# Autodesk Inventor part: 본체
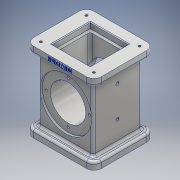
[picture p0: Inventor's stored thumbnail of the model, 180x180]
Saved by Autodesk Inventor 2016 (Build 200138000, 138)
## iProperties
Created: 2017-08
Part Number: 본체
Material: 알루미늄 6061
Document SubType Name: Modeling
Designer: USER
Mass: 790.515 g
Surface Area: 623.184 cm^2
Volume: 292.783 cm^3
Density: 2.7 g/cm^3
Appearance: 알루미늄 - 평지
Author: USER
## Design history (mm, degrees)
sketch "스케치1"
  geometry: L1 (0, 0)-(0, 10); L2 (0, 10)-(8, 10); L3 (8, 10)-(8, 98); L4 (8, 98)-(0, 98); L5 (0, 98)-(0, 108); L6 (0, 108)-(82, 108); L7 (82, 108)-(82, 98); L8 (82, 98)-(74, 98); L9 (74, 98)-(74, 10); L10 (74, 10)-(82, 10); L11 (82, 10)-(82, 0); L12 (82, 0)-(0, 0); L13 (8, 10)-(74, 10); L14 (8, 98)-(74, 98)
  constraints: 28 end point, 8 perpendicular, 4 point on line, 2 horizontal, 1 vertical
  dimensions: "d0" = 108 distance between parallel lines of L12 L6; "d1" = 10 distance between parallel lines of L4 L6; "d2" = 10 distance between parallel lines of L12 L2; "d7" = 8 distance of L3.end L4.end; "d11" = 82 distance between parallel lines of L7 L5; "d12" = 82 distance between parallel lines of L11 L1; "d13" = 66 distance between parallel lines of L3 L9; "d14" = 10 distance between parallel lines of L6 L8
extrude "돌출5" new body sketch "스케치1" stored distance "d73" = 74; taper "d74" = 0 deg
extrude "돌출6" join sketch "스케치1" stored distance "d75" = 92; taper "d76" = 0 deg
sketch "스케치12"
  geometry: 1 further point
node "작업 평면4"
sketch "스케치13"
  geometry: L1 (8, 10)-(8, 98) reference; L2 (8, 54)-(74, 54); L3 (74, 98)-(74, 10) reference; L4 (8, 54)-(8, 89); L5 (8, 89)-(11, 89); L6 (11, 89)-(11, 78); L7 (11, 78)-(71, 78); L8 (71, 78)-(71, 89); L9 (71, 89)-(74, 89); L10 (74, 89)-(74, 54); 1 further point
  constraints: 16 end point, 4 point on line, 3 perpendicular, 2 midpoint, 1 collinear, 1 horizontal
  dimensions: "d78" = 3 distance of L4.end L5.end; "d79" = 3 distance of L8.end L9.end; "d80" = 48 diameter of L7 L2; "d81" = 70 diameter of L5.end L2
revolve "회전2" sketch "스케치13" stored, may be unused: angle "d82" = 90 deg
sketch "스케치14"
  geometry: L1 (24, 19)-(68, 19); L2 (68, 19)-(68, 63); L3 (68, 63)-(24, 63); L4 (24, 63)-(24, 19); L5 (20, 15)-(72, 15); L6 (72, 15)-(72, 67); L7 (72, 67)-(20, 67); L8 (20, 67)-(20, 15); L9 (0, 0)-(0, 82) reference; L10 (0, 0)-(92, 0) reference; 8 further points
  constraints: 16 end point, 7 midpoint, 4 parallel, 2 horizontal, 2 horizontal alignment, 2 perpendicular, 2 vertical alignment
  dimensions: "d83" = 52 distance of L7.end L5.start; "d84" = 52 distance of L6.end L7.end; "d85" = 44 distance of L3.end L1.start; "d86" = 44 distance of L1.start L1.end
extrude "돌출7" cut sketch "스케치14" distance "d87" = 8; taper "d88" = 0 deg
extrude "돌출8" cut sketch "스케치14" stored distance "d89" = 8; taper "d90" = 0 deg; dims "d91" = 48, "d92" = 48
sketch "스케치15"
  geometry: L1 (22, -65)-(70, -65); L2 (70, -65)-(70, -17); L3 (70, -17)-(22, -17); L4 (22, -17)-(22, -65); L5 (0, -82)-(0, 0) reference; L6 (0, -82)-(92, -82) reference; 5 further points
  constraints: 8 end point, 4 midpoint, 2 parallel, 1 horizontal, 1 horizontal alignment, 1 perpendicular, 1 vertical alignment
  dimensions: "d91" = 48 distance of L3.end L1.start; "d92" = 48 distance of L2.end L3.end
extrude "돌출9" cut sketch "스케치15" distance "d93" = 16; taper "d94" = 0 deg
sketch "스케치16"
  geometry: L1 (10, 72)-(82, 72); L2 (82, 72)-(82, 10); L3 (82, 10)-(10, 10); L4 (10, 10)-(10, 72); L5 (0, 82)-(92, 82) reference; L6 (0, 0)-(0, 82) reference; 9 further points
  constraints: 8 end point, 4 coincident, 4 midpoint, 2 parallel, 1 horizontal, 1 horizontal alignment, 1 perpendicular, 1 vertical alignment
  dimensions: "d95" = 72 distance of L1.start L1.end; "d96" = 62 distance of L3.end L1.start
hole "구멍4" sketch "스케치16" at (10, 72), (10, 10), (82, 10), (82, 72) diameter "d97" = 3.242; stored, may be unused: countersink angle "d101" = 90 deg, drill point angle "d103" = 118 deg; dims "d98" = 4, "d99" = 4, "d100" = 2, "d102" = 6
node "작업 평면5"
sketch "스케치17" dims "d104" = 58
  geometry: C1 r 35 at (0, 0) reference; 3 further points
  constraints: 1 coincident, 1 vertical alignment, 2 other
hole "구멍5" sketch "스케치17" at (0, 29) diameter "d105" = 3.242; stored, may be unused: countersink angle "d109" = 90 deg, drill point angle "d111" = 118 deg; dims "d106" = 4, "d107" = 4, "d108" = 2, "d110" = 6
node "작업 평면6"
sketch "스케치18"
  geometry: L1 (-108, 82)-(-108, 0) reference; L2 (0, 0)-(0, 82) reference; 4 further points
  constraints: 2 horizontal alignment, 2 midpoint
  dimensions: "d115" = 38 distance from line of L2 point (-38, 41); "d116" = 42 distance of point (-38, 41) point (-80, 41)
hole "구멍6" sketch "스케치18" at (-80, 41), (-38, 41) diameter "d117" = 4.134; stored, may be unused: countersink angle "d121" = 90 deg, drill point angle "d123" = 118 deg; dims "d118" = 20, "d119" = 4, "d120" = 2, "d122" = 20
fillet "모깎기2" dims "d124" = 10
chamfer "모따기2" distance "d125" = 1; stored, may be unused: second distance "d126" = 2, angle "d127" = 45 deg
fillet "모깎기3" dims "d128" = 3
fillet "모깎기4" dims "d129" = 3
fillet "모깎기5" dims "d130" = 3
fillet "모깎기6" dims "d131" = 3
sketch "스케치19"
  geometry: L1 (0, 0)-(72, 0) reference; L2 (-10, 0)-(-10, -7) reference; 2 further points
  constraints: 1 other
  dimensions: "d132" = 4 distance from line of L1 point (36, -4); "d133" = 46 distance from line of L2 point (36, -4)
feature "엠보싱2" sketch "스케치19" dims "d134" = 0.5, "d135" = 0
fillet "모깎기7" dims "d136" = 3
node "솔리드2"
mirror "대칭3"
pattern_circular "원형 패턴2" dims angle "d113" = 360 deg
mirror "대칭4"
other parameters: "d77" = 0
